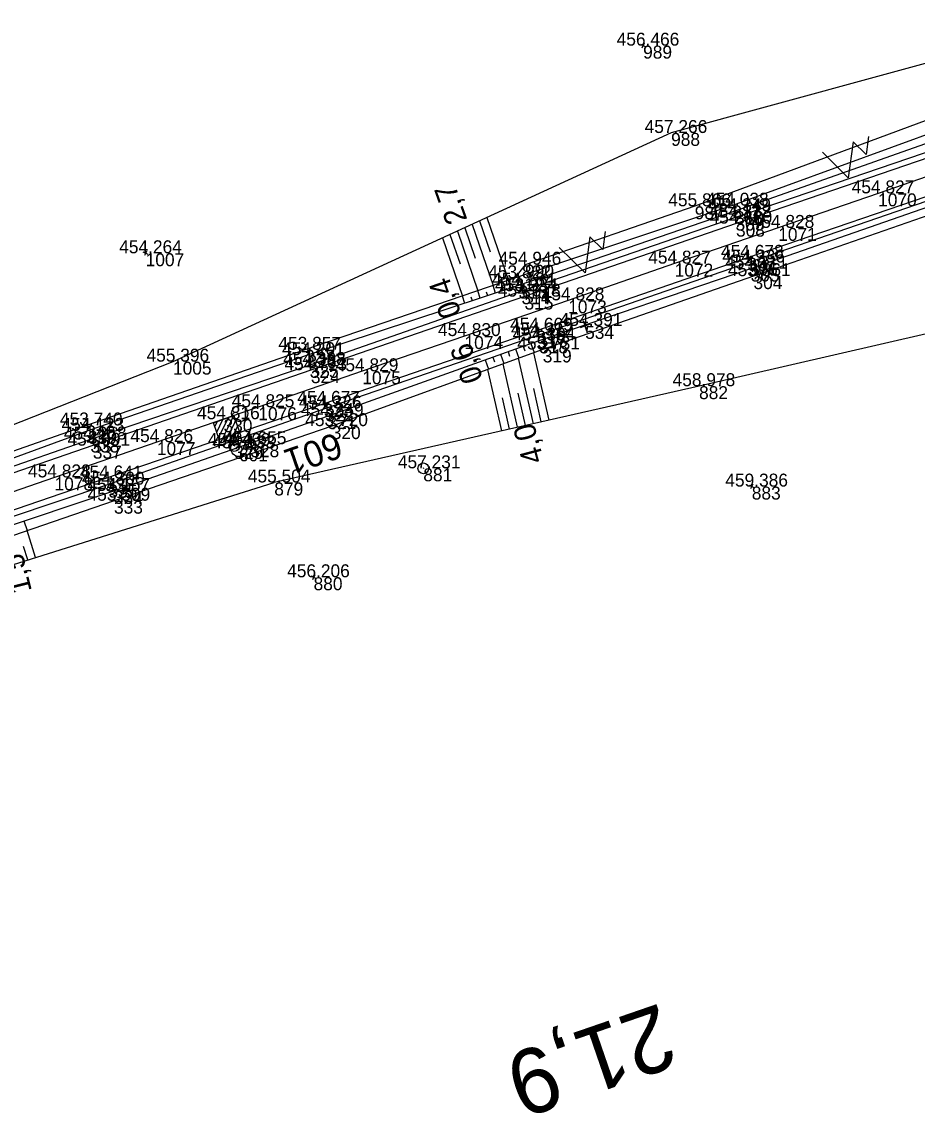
# Model space of a CAD drawing. Extents: x -751615 to -750797, y -1114905 to -1114561.
# Drawn here: x -751505.9 to -751423, y -1114870.9 to -1114769.6 of the extents above; entities that cross this region are included whole.
import ezdxf

# ---------------------------------------------------------------- set-up
doc = ezdxf.new("R2010")
doc.units = 0
for name, color, linetype in [('Vrstva 1', 7, 'Continuous'), ('Vrstva 27', 7, 'Continuous'), ('Vrstva 3', 7, 'Continuous'), ('Vrstva 4', 7, 'Continuous'), ('Vrstva 48', 7, 'Continuous'), ('Vrstva 49', 7, 'Continuous'), ('Vrstva 50', 7, 'Continuous'), ('Vrstva 53', 7, 'Continuous'), ('Vrstva 60', 7, 'Continuous'), ('Vrstva 61', 7, 'Continuous'), ('Vrstva 63', 7, 'Continuous'), ('Vrstva 7', 7, 'Continuous')]:
    doc.layers.add(name, color=color, linetype=linetype)

msp = doc.modelspace()

# ---------------------------------------------------------------- linework, layer by layer
at = {"layer": 'Vrstva 1'}
msp.add_lwpolyline([(-751416.74, -1114782.09), (-751426.63, -1114785.5), (-751435.88, -1114788.7), (-751445.47, -1114792.01), (-751455.33, -1114795.41), (-751464.93, -1114798.72), (-751474.39, -1114801.98), (-751484.02, -1114805.31), (-751487.24, -1114806.42), (-751493.41, -1114808.54), (-751502.89, -1114811.81), (-751512.36, -1114815.08), (-751523.74, -1114819.01), (-751530.66, -1114821.4), (-751541.12, -1114825), (-751550.73, -1114828.32), (-751560.17, -1114831.58), (-751569.85, -1114834.92), (-751579.12, -1114838.11), (-751588.6, -1114841.38)], dxfattribs=at)
at = {"layer": 'Vrstva 27'}
msp.add_line((-751486.19, -1114808.88), (-751486.29, -1114808.91), dxfattribs=at)
msp.add_circle((-751486.24, -1114808.9), 0.5, dxfattribs=at)
at = {"layer": 'Vrstva 3'}
for p, q in [((-751487.53, -1114808.63), (-751486.29, -1114806.09)), ((-751488.05, -1114807.13), (-751487.8, -1114806.61)), ((-751487.87, -1114807.63), (-751487.29, -1114806.44)), ((-751487.7, -1114808.13), (-751486.79, -1114806.26)), ((-751487.03, -1114808.46), (-751486.12, -1114806.59)), ((-751486.52, -1114808.29), (-751485.94, -1114807.09)), ((-751486.02, -1114808.11), (-751485.77, -1114807.59))]:
    msp.add_line(p, q, dxfattribs=at)
msp.add_lwpolyline([(-751488.18, -1114806.74), (-751486.29, -1114806.09), (-751485.64, -1114807.98), (-751487.53, -1114808.63)], close=True, dxfattribs=at)
at = {"layer": 'Vrstva 4'}
for points in [[(-751187.89, -1114700.58), (-751206.03, -1114707.04), (-751231.23, -1114715.6), (-751249.54, -1114721.97), (-751267.72, -1114728.47), (-751285.3, -1114734.54), (-751305.69, -1114741.51), (-751323.63, -1114747.67), (-751344.16, -1114754.78), (-751362.44, -1114761.12), (-751382.65, -1114768), (-751419.83, -1114780.91), (-751439.84, -1114787.75), (-751459.65, -1114794.56), (-751479.26, -1114801.4), (-751499.56, -1114808.3), (-751517.66, -1114814.61), (-751524.47, -1114817.14), (-751524.91, -1114817.65)], [(-751186.45, -1114705.27), (-751204.57, -1114711.26), (-751229.26, -1114719.97), (-751248.51, -1114726.39), (-751266.03, -1114732.59), (-751283.83, -1114738.73), (-751304.21, -1114745.77), (-751322.37, -1114751.9), (-751342.61, -1114758.9), (-751360.96, -1114765.17), (-751381.11, -1114772.12), (-751418.54, -1114785), (-751438.61, -1114791.91), (-751458.17, -1114798.66), (-751477.81, -1114805.42), (-751497.9, -1114812.48), (-751516.51, -1114818.69), (-751522.39, -1114820.61), (-751523.2, -1114820.52)], [(-751205.8, -1114707.6), (-751230.97, -1114716.26), (-751249.42, -1114722.68), (-751267.45, -1114728.87), (-751285.11, -1114734.87), (-751305.56, -1114741.94), (-751323.35, -1114748.14), (-751343.96, -1114755.23), (-751362.41, -1114761.58), (-751382.45, -1114768.54), (-751419.68, -1114781.41), (-751439.79, -1114788.3), (-751459.37, -1114795.06), (-751479.15, -1114801.88), (-751499.34, -1114808.87), (-751517.57, -1114815.16), (-751524.91, -1114817.65)], [(-751204.68, -1114710.75), (-751229.56, -1114719.28), (-751248.53, -1114725.94), (-751266.25, -1114732.04), (-751284.07, -1114738.15), (-751304.21, -1114745.08), (-751322.47, -1114751.34), (-751342.64, -1114758.27), (-751361.14, -1114764.64), (-751381.34, -1114771.71), (-751418.71, -1114784.62), (-751438.73, -1114791.47), (-751458.26, -1114798.22), (-751477.95, -1114805), (-751498.18, -1114811.91), (-751516.63, -1114818.24), (-751523.2, -1114820.52)]]:
    msp.add_lwpolyline(points, dxfattribs=at)
at = {"layer": 'Vrstva 48'}
for p, q in [((-751462.85, -1114787.74), (-751460.86, -1114793.57)), ((-751465.59, -1114789), (-751463.7, -1114794.53)), ((-751464.91, -1114788.68), (-751463.95, -1114791.49)), ((-751464.22, -1114788.37), (-751462.28, -1114794.05)), ((-751463.54, -1114788.05), (-751462.56, -1114790.93)), ((-751466.96, -1114789.63), (-751465.12, -1114795.02)), ((-751466.28, -1114789.31), (-751465.34, -1114792.04)), ((-751462.05, -1114794.75), (-751462.28, -1114794.05)), ((-751460.62, -1114794.28), (-751460.86, -1114793.57)), ((-751464.9, -1114795.69), (-751465.12, -1114795.02)), ((-751463.47, -1114795.22), (-751463.7, -1114794.53)), ((-751462.76, -1114794.98), (-751462.88, -1114794.64)), ((-751461.33, -1114794.51), (-751461.45, -1114794.16)), ((-751464.18, -1114795.45), (-751464.3, -1114795.11)), ((-751460.2, -1114799.9), (-751459.89, -1114800.76)), ((-751459.49, -1114799.65), (-751459.34, -1114800.08)), ((-751458.78, -1114799.4), (-751458.48, -1114800.25)), ((-751463.02, -1114800.91), (-751462.71, -1114801.78)), ((-751462.31, -1114800.66), (-751462.16, -1114801.09)), ((-751461.61, -1114800.41), (-751461.3, -1114801.27)), ((-751460.9, -1114800.16), (-751460.75, -1114800.59)), ((-751458.55, -1114806.84), (-751459.93, -1114800.77)), ((-751457.09, -1114806.51), (-751458.51, -1114800.26)), ((-751461.48, -1114807.5), (-751462.77, -1114801.81)), ((-751460.01, -1114807.17), (-751461.35, -1114801.29)), ((-751459.28, -1114807.01), (-751459.96, -1114804.02)), ((-751457.82, -1114806.67), (-751458.52, -1114803.59)), ((-751460.75, -1114807.34), (-751461.4, -1114804.44)), ((-751505.72, -1114815.84), (-751505.42, -1114816.74)), ((-751504.64, -1114819.24), (-751505.43, -1114816.74)), ((-751505.36, -1114819.46), (-751505.75, -1114818.22))]:
    msp.add_line(p, q, dxfattribs=at)
at = {"layer": 'Vrstva 49'}
for p, q in [((-751448.17, -1114771.93), (-751448.61, -1114771.71)), ((-751448.28, -1114771.59), (-751448.5, -1114772.04)), ((-751494.23, -1114791.16), (-751494.68, -1114790.94)), ((-751494.34, -1114790.82), (-751494.56, -1114791.27)), ((-751438.1, -1114812.77), (-751438.55, -1114812.55)), ((-751438.22, -1114812.43), (-751438.44, -1114812.88)), ((-751478.68, -1114821.17), (-751479.12, -1114820.95)), ((-751478.79, -1114820.84), (-751479.01, -1114821.29))]:
    msp.add_line(p, q, dxfattribs=at)
for points in [[(-751234.95, -1114713.28), (-751245.48, -1114717.14), (-751281.47, -1114726.53), (-751304.18, -1114733.33), (-751349.01, -1114749.46), (-751398.2, -1114766.87), (-751445.8, -1114779.91), (-751491.92, -1114801.09), (-751522.47, -1114813.15), (-751523.88, -1114811.23), (-751530.06, -1114804.52)], [(-751231.53, -1114714.48), (-751249.64, -1114721.46), (-751267.89, -1114727.82), (-751285.51, -1114733.95), (-751305.91, -1114740.8), (-751324, -1114747.03), (-751344.27, -1114754.11), (-751362.59, -1114760.52), (-751382.59, -1114767.44), (-751402.41, -1114774.04), (-751420.23, -1114780.2), (-751439.89, -1114787.15), (-751459.92, -1114794.04), (-751479.47, -1114800.49), (-751499.79, -1114807.5), (-751517.87, -1114814.1), (-751523.11, -1114815.97), (-751524.21, -1114815.64), (-751526.18, -1114811.44)], [(-751244.9, -1114718.57), (-751249.94, -1114720.63), (-751268.48, -1114726.93), (-751276.66, -1114729.62), (-751285.76, -1114733.33), (-751305.98, -1114740.17), (-751324.13, -1114746.66), (-751344.39, -1114753.73), (-751362.68, -1114760.23), (-751382.77, -1114766.9), (-751402.56, -1114773.56), (-751420.5, -1114779.46), (-751440.12, -1114786.64), (-751460.29, -1114793.37), (-751479.7, -1114799.99), (-751499.94, -1114807), (-751518.24, -1114813.43), (-751522.74, -1114814.82), (-751523.67, -1114814.11), (-751524.93, -1114811.32)], [(-751523.9, -1114821.95), (-751516.26, -1114819.37), (-751497.39, -1114813.06), (-751477.62, -1114806.13), (-751458.02, -1114799.12), (-751438.43, -1114792.47), (-751418.48, -1114785.51), (-751400.56, -1114779.53), (-751380.1, -1114772.49), (-751360.67, -1114765.9), (-751342.47, -1114759.51), (-751322.29, -1114752.46), (-751304.11, -1114746.3), (-751283.78, -1114739.21), (-751265.74, -1114733.22), (-751248.29, -1114727.04), (-751240.07, -1114724.3)], [(-751204.75, -1114724.61), (-751227.2, -1114725.51), (-751238.2, -1114726.49), (-751253.2, -1114735.38), (-751297.85, -1114756.71), (-751332.9, -1114772.39), (-751375.5, -1114786.51), (-751400.7, -1114793.56), (-751443.21, -1114803.36), (-751482.54, -1114812.28)], [(-751240.24, -1114725.65), (-751248.02, -1114728.05), (-751265.49, -1114734.04), (-751283.47, -1114739.99), (-751303.76, -1114746.77), (-751322.17, -1114753.1), (-751342.49, -1114760), (-751360.52, -1114766.36), (-751379.96, -1114773.04), (-751400.34, -1114780.09), (-751418.29, -1114786.26), (-751438.17, -1114793.17), (-751457.68, -1114799.96), (-751477.22, -1114807.06), (-751497.38, -1114813.97), (-751516.22, -1114820.45), (-751522.92, -1114822.93), (-751523.9, -1114821.95)], [(-751276.66, -1114729.62), (-751280.14, -1114730.3), (-751302.67, -1114736.54), (-751347.76, -1114752.37), (-751397.37, -1114769.54), (-751443.61, -1114786.7), (-751459.32, -1114792.11), (-751460.29, -1114793.37)], [(-751523.49, -1114823.84), (-751522.7, -1114824.92), (-751482.54, -1114812.28)]]:
    msp.add_lwpolyline(points, dxfattribs=at)
at = {"layer": 'Vrstva 50'}
for points in [[(-751427.53, -1114780.24), (-751427.75, -1114781.9), (-751428.95, -1114780.73), (-751429.39, -1114784.05), (-751431.78, -1114781.7)], [(-751451.9, -1114789.04), (-751452.12, -1114790.7), (-751453.32, -1114789.53), (-751453.76, -1114792.85), (-751456.15, -1114790.5)]]:
    msp.add_lwpolyline(points, dxfattribs=at)
at = {"layer": 'Vrstva 53'}
msp.add_line((-751468.69, -1114810.95), (-751468.79, -1114810.99), dxfattribs=at)
msp.add_circle((-751468.74, -1114810.97), 0.499, dxfattribs=at)
at = {"layer": 'Vrstva 60'}
for p, q in [((-751448.39, -1114771.82), (-751448.39, -1114771.82)), ((-751445.8, -1114779.91), (-751445.8, -1114779.91)), ((-751426.63, -1114785.5), (-751426.63, -1114785.5)), ((-751443.61, -1114786.7), (-751443.61, -1114786.7)), ((-751440.12, -1114786.64), (-751440.12, -1114786.64)), ((-751439.89, -1114787.15), (-751439.89, -1114787.15)), ((-751439.84, -1114787.75), (-751439.84, -1114787.75)), ((-751439.79, -1114788.3), (-751439.79, -1114788.3)), ((-751435.88, -1114788.7), (-751435.88, -1114788.7)), ((-751494.45, -1114791.05), (-751494.45, -1114791.05)), ((-751445.47, -1114792.01), (-751445.47, -1114792.01)), ((-751438.73, -1114791.47), (-751438.73, -1114791.47)), ((-751438.61, -1114791.91), (-751438.61, -1114791.91)), ((-751459.32, -1114792.11), (-751459.32, -1114792.11)), ((-751438.43, -1114792.47), (-751438.43, -1114792.47)), ((-751460.29, -1114793.37), (-751460.29, -1114793.37)), ((-751459.92, -1114794.04), (-751459.92, -1114794.04)), ((-751438.17, -1114793.17), (-751438.17, -1114793.17)), ((-751459.65, -1114794.56), (-751459.65, -1114794.56)), ((-751459.37, -1114795.06), (-751459.37, -1114795.06)), ((-751455.33, -1114795.41), (-751455.33, -1114795.41)), ((-751453.76, -1114797.78), (-751453.76, -1114797.78)), ((-751464.93, -1114798.72), (-751464.93, -1114798.72)), ((-751458.26, -1114798.22), (-751458.26, -1114798.22)), ((-751458.17, -1114798.66), (-751458.17, -1114798.66)), ((-751458.02, -1114799.12), (-751458.02, -1114799.12)), ((-751479.7, -1114799.99), (-751479.7, -1114799.99)), ((-751457.68, -1114799.96), (-751457.68, -1114799.96)), ((-751491.92, -1114801.09), (-751491.92, -1114801.09)), ((-751479.47, -1114800.49), (-751479.47, -1114800.49)), ((-751479.26, -1114801.4), (-751479.26, -1114801.4)), ((-751479.15, -1114801.88), (-751479.15, -1114801.88)), ((-751474.39, -1114801.98), (-751474.39, -1114801.98)), ((-751443.21, -1114803.36), (-751443.21, -1114803.36)), ((-751477.95, -1114805), (-751477.95, -1114805)), ((-751484.02, -1114805.31), (-751484.02, -1114805.31)), ((-751477.81, -1114805.42), (-751477.81, -1114805.42)), ((-751477.62, -1114806.13), (-751477.62, -1114806.13)), ((-751499.94, -1114807), (-751499.94, -1114807)), ((-751487.24, -1114806.42), (-751487.24, -1114806.42)), ((-751477.22, -1114807.06), (-751477.22, -1114807.06)), ((-751499.79, -1114807.5), (-751499.79, -1114807.5)), ((-751499.56, -1114808.3), (-751499.56, -1114808.3)), ((-751499.34, -1114808.87), (-751499.34, -1114808.87)), ((-751493.41, -1114808.54), (-751493.41, -1114808.54)), ((-751486.24, -1114808.9), (-751486.24, -1114808.9)), ((-751485.81, -1114809.12), (-751485.81, -1114809.12)), ((-751484.76, -1114808.74), (-751484.76, -1114808.74)), ((-751468.74, -1114810.97), (-751468.74, -1114810.97)), ((-751502.89, -1114811.81), (-751502.89, -1114811.81)), ((-751498.18, -1114811.91), (-751498.18, -1114811.91)), ((-751482.54, -1114812.28), (-751482.54, -1114812.28)), ((-751497.9, -1114812.48), (-751497.9, -1114812.48)), ((-751497.39, -1114813.06), (-751497.39, -1114813.06)), ((-751438.33, -1114812.66), (-751438.33, -1114812.66)), ((-751497.38, -1114813.97), (-751497.38, -1114813.97)), ((-751478.9, -1114821.06), (-751478.9, -1114821.06))]:
    msp.add_line(p, q, dxfattribs=at)
at = {"layer": 'Vrstva 63'}
msp.add_line((-751485.77, -1114809.11), (-751485.86, -1114809.14), dxfattribs=at)
msp.add_circle((-751485.81, -1114809.12), 0.756, dxfattribs=at)
at = {"layer": 'Vrstva 7'}
for p, q in [((-751453.28, -1114797.62), (-751454.23, -1114797.95)), ((-751453.59, -1114798.26), (-751453.92, -1114797.31)), ((-751484.71, -1114808.72), (-751484.81, -1114808.75))]:
    msp.add_line(p, q, dxfattribs=at)
for centre, radius in [((-751485.74, -1114805.9), 0.75), ((-751484.76, -1114808.74), 0.5)]:
    msp.add_circle(centre, radius, dxfattribs=at)

# ---------------------------------------------------------------- texts
at = {"layer": 'Vrstva 48'}
for s, rotation, p in [('2,7', 109.6695, (-751464.64, -1114787.94)), ('0,4', 108.835, (-751465.2, -1114796.67)), ('0,6', 109.6685, (-751463.18, -1114802.69)), ('4,0', 104.969, (-751457.57, -1114810.25)), ('1,5', 103.9842, (-751504.97, -1114822.32))]:
    msp.add_text(s, height=2, rotation=rotation, dxfattribs=at).set_placement(p)
at = {"layer": 'Vrstva 60'}
for s, p in [('989', (-751448.39, -1114773.02)), ('988', (-751445.8, -1114781.1)), ('1070', (-751426.63, -1114786.7)), ('987', (-751443.61, -1114787.9)), ('311', (-751440.12, -1114787.83)), ('310', (-751439.89, -1114788.35)), ('309', (-751439.84, -1114788.95)), ('308', (-751439.79, -1114789.51)), ('1071', (-751435.88, -1114789.9)), ('1007', (-751494.45, -1114792.25)), ('1072', (-751445.47, -1114793.21)), ('307', (-751438.73, -1114792.67)), ('306', (-751438.61, -1114793.11)), ('990', (-751459.32, -1114793.31)), ('305', (-751438.43, -1114793.67)), ('312', (-751460.29, -1114794.57)), ('313', (-751459.92, -1114795.25)), ('304', (-751438.17, -1114794.37)), ('314', (-751459.65, -1114795.77)), ('315', (-751459.37, -1114796.26)), ('1073', (-751455.33, -1114796.61)), ('534', (-751453.76, -1114798.98)), ('1074', (-751464.93, -1114799.92)), ('316', (-751458.26, -1114799.42)), ('317', (-751458.17, -1114799.86)), ('318', (-751458.02, -1114800.32)), ('327', (-751479.7, -1114801.19)), ('319', (-751457.68, -1114801.16)), ('1005', (-751491.92, -1114802.29)), ('326', (-751479.47, -1114801.69)), ('325', (-751479.26, -1114802.59)), ('324', (-751479.15, -1114803.08)), ('1075', (-751474.39, -1114803.18)), ('882', (-751443.21, -1114804.56)), ('323', (-751477.95, -1114806.2)), ('1076', (-751484.02, -1114806.51)), ('322', (-751477.81, -1114806.62)), ('321', (-751477.62, -1114807.33)), ('340', (-751499.94, -1114808.2)), ('330', (-751487.24, -1114807.62)), ('320', (-751477.22, -1114808.26)), ('339', (-751499.79, -1114808.7)), ('338', (-751499.56, -1114809.5)), ('337', (-751499.34, -1114810.07)), ('1077', (-751493.41, -1114809.74)), ('329', (-751486.24, -1114810.1)), ('601', (-751485.81, -1114810.32)), ('328', (-751484.76, -1114809.94)), ('881', (-751468.74, -1114812.17)), ('1078', (-751502.89, -1114813.01)), ('336', (-751498.18, -1114813.11)), ('879', (-751482.54, -1114813.48)), ('335', (-751497.9, -1114813.68)), ('334', (-751497.39, -1114814.26)), ('883', (-751438.33, -1114813.86)), ('333', (-751497.38, -1114815.17)), ('880', (-751478.9, -1114822.26))]:
    msp.add_text(s, height=1.2, dxfattribs=at).set_placement(p)
at = {"layer": 'Vrstva 61'}
for s, p in [('456.466', (-751450.84, -1114771.82)), ('457.266', (-751448.25, -1114779.91)), ('454.827', (-751429.08, -1114785.5)), ('455.866', (-751446.06, -1114786.7)), ('454.038', (-751442.57, -1114786.64)), ('454.349', (-751442.35, -1114787.15)), ('454.333', (-751442.29, -1114787.75)), ('454.680', (-751442.24, -1114788.3)), ('454.828', (-751438.34, -1114788.7)), ('454.264', (-751496.9, -1114791.05)), ('454.946', (-751461.77, -1114792.11)), ('454.827', (-751447.92, -1114792.01)), ('454.678', (-751441.18, -1114791.47)), ('454.336', (-751441.06, -1114791.91)), ('454.311', (-751440.79, -1114792.47)), ('453.861', (-751440.53, -1114793.17)), ('453.822', (-751462.73, -1114793.37)), ('454.184', (-751462.37, -1114794.04)), ('454.334', (-751462.1, -1114794.56)), ('454.678', (-751461.83, -1114795.06)), ('454.828', (-751457.78, -1114795.41)), ('454.669', (-751460.71, -1114798.22)), ('454.391', (-751456.11, -1114797.78)), ('454.830', (-751467.38, -1114798.72)), ('454.312', (-751460.62, -1114798.66)), ('454.304', (-751460.47, -1114799.12)), ('453.857', (-751482.16, -1114799.99)), ('453.731', (-751460.04, -1114799.96)), ('455.396', (-751494.37, -1114801.09)), ('454.201', (-751481.82, -1114800.49)), ('454.398', (-751481.72, -1114801.4)), ('454.713', (-751481.6, -1114801.88)), ('454.829', (-751476.85, -1114801.98)), ('458.978', (-751445.66, -1114803.36)), ('454.825', (-751486.48, -1114805.31)), ('454.677', (-751480.41, -1114805)), ('454.816', (-751489.69, -1114806.42)), ('454.326', (-751480.27, -1114805.42)), ('454.249', (-751480.07, -1114806.13)), ('453.740', (-751502.39, -1114807)), ('453.720', (-751479.67, -1114807.06)), ('454.123', (-751502.24, -1114807.5)), ('454.258', (-751502.02, -1114808.3)), ('454.691', (-751501.69, -1114808.87)), ('454.826', (-751495.86, -1114808.54)), ('454.469', (-751488.69, -1114808.9)), ('454.133', (-751488.27, -1114809.12)), ('454.655', (-751487.22, -1114808.74)), ('457.231', (-751471.1, -1114810.97)), ('454.828', (-751505.34, -1114811.81)), ('454.641', (-751500.54, -1114811.91)), ('454.300', (-751500.35, -1114812.48)), ('455.504', (-751484.99, -1114812.28)), ('454.157', (-751499.84, -1114813.06)), ('459.386', (-751440.78, -1114812.66)), ('453.509', (-751499.83, -1114813.97)), ('456.206', (-751481.35, -1114821.06))]:
    msp.add_text(s, height=1.2, dxfattribs=at).set_placement(p)
at = {"layer": 'Vrstva 63'}
msp.add_text('601', height=2.4, rotation=199.028, dxfattribs=at).set_placement((-751476.78, -1114807.6))
at = {"layer": 'Vrstva 7'}
msp.add_text('21,9', height=6, rotation=199.0157, dxfattribs=at).set_placement((-751446.78, -1114860.47))

doc.saveas('drawing.dxf')
